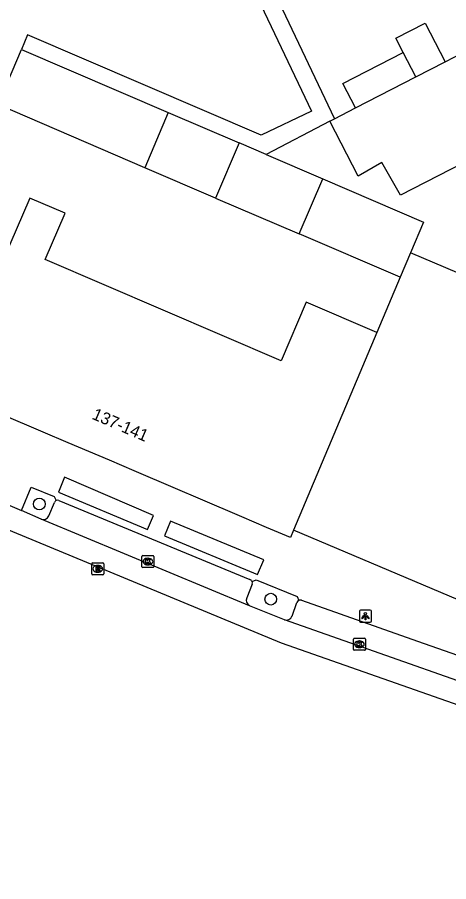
# Model space of a CAD drawing. Extents: x 161771 to 163125, y 382479 to 383177.
# Drawn here: x 162290.1 to 162326.1, y 382570.3 to 382642.4 of the extents above; entities that cross this region are included whole.
import ezdxf

# ---------------------------------------------------------------- set-up
doc = ezdxf.new("R2010")
doc.units = 0
for name, color, linetype in [('IMGEO_Boom', 7, 'Continuous'), ('IMGEO_Kolk', 7, 'Continuous'), ('IMGEO_Lichtpunt', 7, 'Continuous'), ('IMGEO_Pand', 7, 'Continuous'), ('IMGEO_Pand_nummerreeks', 7, 'Continuous'), ('IMGEO_Parkeervlak_open', 7, 'Continuous'), ('IMGEO_Rijbaan_lokaal_gesloten', 7, 'Continuous'), ('IMGEO_Rioolput', 7, 'Continuous'), ('IMGEO_Voetpad_open', 7, 'Continuous')]:
    doc.layers.add(name, color=color, linetype=linetype)

msp = doc.modelspace()

# ---------------------------------------------------------------- linework, layer by layer
at = {"layer": 'IMGEO_Boom'}
for centre in [(162291.967, 382601.804), (162311.264, 382593.877)]:
    msp.add_circle(centre, 0.489, dxfattribs=at)
at = {"layer": 'IMGEO_Kolk'}
for p, q in [((162300.598, 382597.509), (162301.45, 382597.509)), ((162300.523, 382596.583), (162300.523, 382597.435)), ((162301.011, 382597.289), (162301.036, 382597.289)), ((162301.524, 382597.435), (162301.524, 382596.583)), ((162301.45, 382596.509), (162300.598, 382596.509)), ((162301.034, 382596.729), (162301.009, 382596.729)), ((162318.157, 382589.69), (162318.157, 382590.542)), ((162318.232, 382590.616), (162319.084, 382590.616)), ((162318.645, 382590.396), (162318.67, 382590.396)), ((162319.158, 382590.542), (162319.158, 382589.69)), ((162319.084, 382589.616), (162318.232, 382589.616)), ((162318.668, 382589.836), (162318.643, 382589.836))]:
    msp.add_line(p, q, dxfattribs=at)
for points in [[(162300.598, 382597.509), (162301.45, 382597.509)], [(162300.523, 382596.583), (162300.523, 382597.435)], [(162300.844, 382597.209), (162300.967, 382597.209), (162300.967, 382597.058), (162301.097, 382597.209), (162301.261, 382597.209), (162301.115, 382597.058), (162301.268, 382596.809), (162301.116, 382596.809), (162301.031, 382596.973), (162300.967, 382596.906), (162300.967, 382596.809), (162300.844, 382596.809), (162300.844, 382597.209)], [(162301.524, 382597.435), (162301.524, 382596.583)], [(162301.45, 382596.509), (162300.598, 382596.509)], [(162318.157, 382589.69), (162318.157, 382590.542)], [(162318.232, 382590.616), (162319.084, 382590.616)], [(162318.478, 382590.316), (162318.601, 382590.316), (162318.601, 382590.165), (162318.731, 382590.316), (162318.895, 382590.316), (162318.749, 382590.165), (162318.902, 382589.916), (162318.75, 382589.916), (162318.665, 382590.08), (162318.601, 382590.013), (162318.601, 382589.916), (162318.478, 382589.916), (162318.478, 382590.316)], [(162319.158, 382590.542), (162319.158, 382589.69)], [(162319.084, 382589.616), (162318.232, 382589.616)]]:
    msp.add_lwpolyline(points, dxfattribs=at)
for centre, start, end in [((162300.6, 382597.433), 91.55205, 178.44795), ((162300.6, 382597.433), 91.55205, 178.44795), ((162301.448, 382597.433), 1.55205, 88.44795), ((162301.448, 382597.433), 1.55205, 88.44795), ((162300.6, 382596.585), 181.55205, 268.44795), ((162300.6, 382596.585), 181.55205, 268.44795), ((162301.448, 382596.585), 271.55205, 358.44795), ((162301.448, 382596.585), 271.55205, 358.44795), ((162318.234, 382590.54), 91.55205, 178.44795), ((162318.234, 382590.54), 91.55205, 178.44795), ((162319.082, 382590.54), 1.55205, 88.44795), ((162319.082, 382590.54), 1.55205, 88.44795), ((162318.234, 382589.692), 181.55205, 268.44795), ((162318.234, 382589.692), 181.55205, 268.44795), ((162319.082, 382589.692), 271.55205, 358.44795), ((162319.082, 382589.692), 271.55205, 358.44795)]:
    msp.add_arc(centre, 0.0765, start, end, dxfattribs=at)
for centre, major_axis, ratio, start_param, end_param in [((162301.01, 382597.009), (-0.387, 0.002), 0.722429, 4.712389, 7.853982), ((162301.035, 382597.009), (-0.39, 0.002), 0.717154, 1.570796, 4.712389), ((162318.644, 382590.116), (-0.387, 0.002), 0.722429, 4.712389, 7.853982), ((162318.669, 382590.116), (-0.39, 0.002), 0.717154, 1.570796, 4.712389)]:
    msp.add_ellipse(centre, major_axis=major_axis, ratio=ratio, start_param=start_param, end_param=end_param, dxfattribs=at)
at = {"layer": 'IMGEO_Lichtpunt'}
for p, q in [((162318.662, 382592.866), (162318.662, 382592.059)), ((162318.662, 382592.866), (162318.662, 382592.059)), ((162319.564, 382592.961), (162318.756, 382592.961)), ((162319.564, 382592.961), (162318.756, 382592.961)), ((162319.658, 382592.059), (162319.658, 382592.866)), ((162319.658, 382592.059), (162319.658, 382592.866)), ((162318.756, 382591.965), (162319.564, 382591.965)), ((162318.756, 382591.965), (162319.564, 382591.965))]:
    msp.add_line(p, q, dxfattribs=at)
for points in [[(162319.036, 382592.53), (162319.075, 382592.502), (162318.887, 382592.24), (162318.849, 382592.267), (162319.036, 382592.53)], [(162319.138, 382592.482), (162319.185, 382592.482), (162319.185, 382592.16), (162319.138, 382592.16), (162319.138, 382592.482)], [(162319.248, 382592.502), (162319.286, 382592.529), (162319.473, 382592.267), (162319.434, 382592.239), (162319.248, 382592.502)]]:
    msp.add_lwpolyline(points, dxfattribs=at)
msp.add_circle((162319.161, 382592.664), 0.0994, dxfattribs=at)
for centre, start, end in [((162318.756, 382592.866), 90, 180), ((162318.756, 382592.866), 90, 180), ((162319.564, 382592.866), 0, 90), ((162319.564, 382592.866), 0, 90), ((162318.756, 382592.059), 180, 270), ((162318.756, 382592.059), 180, 270), ((162319.564, 382592.059), 270, 0), ((162319.564, 382592.059), 270, 360)]:
    msp.add_arc(centre, 0.0946, start, end, dxfattribs=at)
at = {"layer": 'IMGEO_Pand'}
for points in [[(162355.836, 382644.864), (162351.387, 382642.583), (162322.08, 382627.559), (162320.518, 382630.266), (162318.547, 382629.128), (162316.196, 382633.711)], [(162322.301, 382639.446), (162321.696, 382640.618), (162324.138, 382641.877), (162325.796, 382638.664)], [(162325.796, 382638.664), (162329.566, 382640.609)], [(162300.776, 382629.833), (162288.5, 382635.102), (162290.472, 382639.696)], [(162290.472, 382639.696), (162302.709, 382634.444)], [(162318.328, 382634.811), (162317.274, 382636.853), (162322.301, 382639.446)], [(162323.354, 382637.404), (162322.301, 382639.446)], [(162323.354, 382637.404), (162325.796, 382638.664)], [(162318.328, 382634.811), (162323.354, 382637.404)], [(162302.709, 382634.444), (162300.776, 382629.833)], [(162302.709, 382634.444), (162308.629, 382631.902)], [(162316.579, 382633.909), (162318.328, 382634.811)], [(162316.196, 382633.711), (162316.579, 382633.909)], [(162308.629, 382631.902), (162306.667, 382627.305)], [(162310.889, 382630.932), (162308.629, 382631.902)], [(162310.889, 382630.932), (162315.613, 382628.905)], [(162306.667, 382627.305), (162300.776, 382629.833)], [(162313.635, 382624.314), (162315.613, 382628.905)], [(162315.613, 382628.905), (162324.013, 382625.299), (162322.929, 382622.738)], [(162320.101, 382616.097), (162314.228, 382618.615), (162312.143, 382613.751), (162292.459, 382622.19), (162294.111, 382626.044), (162291.175, 382627.303), (162289.511, 382623.447), (162284.254, 382611.213)], [(162306.667, 382627.305), (162313.635, 382624.314)], [(162322.058, 382620.699), (162313.635, 382624.314)], [(162322.929, 382622.738), (162322.058, 382620.699)], [(162379.028, 382608.247), (162375.863, 382604.377), (162373.376, 382601.335), (162322.929, 382622.738)], [(162322.058, 382620.699), (162320.101, 382616.097)], [(162320.101, 382616.097), (162313.172, 382599.641)], [(162313.172, 382599.641), (162312.902, 382599.006), (162310.913, 382599.855), (162308.846, 382600.737), (162305.395, 382602.21), (162303.325, 382603.093), (162299.876, 382604.565), (162297.808, 382605.447), (162294.365, 382606.912), (162292.279, 382607.8), (162288.83, 382609.267), (162286.762, 382610.146), (162284.254, 382611.213)], [(162368.518, 382576.348), (162368.466, 382576.233), (162313.172, 382599.641)]]:
    msp.add_lwpolyline(points, dxfattribs=at)
at = {"layer": 'IMGEO_Parkeervlak_open'}
for points in [[(162292.774, 382600.819), (162293.221, 382601.933)], [(162309.725, 382595.123), (162309.258, 382593.996)], [(162313.036, 382592.464), (162313.451, 382593.597)]]:
    msp.add_lwpolyline(points, dxfattribs=at)
for centre, radius, start, end in [((162293.51, 382601.807), 0.315, 114.5801, 156.49753), ((162292.304, 382601.029), 0.514, 247.7872, 335.87512), ((162309.401, 382595.207), 0.335, 345.50052, 25.92067), ((162309.715, 382593.79), 0.501, 155.76764, 245.2114), ((162313.753, 382593.485), 0.321, 119.95346, 159.69697), ((162312.554, 382592.655), 0.518, 253.69279, 338.33551)]:
    msp.add_arc(centre, radius, start, end, dxfattribs=at)
at = {"layer": 'IMGEO_Rijbaan_lokaal_gesloten'}
for points in [[(162370.099, 382570.33), (162336, 382581.86), (162312.157, 382590.208), (162289.771, 382599.475), (162259.358, 382612.5), (162215.386, 382631.365)], [(162277.062, 382607.009), (162290.489, 382601.256)], [(162292.11, 382600.553), (162290.489, 382601.256)], [(162309.505, 382593.335), (162292.11, 382600.553)], [(162312.409, 382592.158), (162309.505, 382593.335)], [(162335.784, 382583.935), (162312.409, 382592.158)]]:
    msp.add_lwpolyline(points, dxfattribs=at)
at = {"layer": 'IMGEO_Rioolput'}
for p, q in [((162296.336, 382595.981), (162296.336, 382596.833)), ((162296.411, 382596.907), (162297.263, 382596.907)), ((162297.337, 382596.833), (162297.337, 382595.981)), ((162296.847, 382596.127), (162296.822, 382596.127)), ((162296.824, 382596.687), (162296.849, 382596.687)), ((162297.263, 382595.907), (162296.411, 382595.907))]:
    msp.add_line(p, q, dxfattribs=at)
for points in [[(162296.336, 382595.981), (162296.336, 382596.833)], [(162296.411, 382596.907), (162297.263, 382596.907)], [(162297.337, 382596.833), (162297.337, 382595.981)], [(162296.925, 382596.605), (162296.673, 382596.607), (162296.673, 382596.207)], [(162296.673, 382596.207), (162296.797, 382596.207), (162296.797, 382596.369), (162296.808, 382596.369)], [(162296.851, 382596.526), (162296.797, 382596.526), (162296.797, 382596.445)], [(162296.797, 382596.445), (162296.849, 382596.445)], [(162296.855, 382596.34), (162296.926, 382596.207), (162297.066, 382596.207), (162297.001, 382596.333)], [(162297.263, 382595.907), (162296.411, 382595.907)]]:
    msp.add_lwpolyline(points, dxfattribs=at)
for centre, radius, start, end in [((162296.413, 382596.831), 0.0765, 91.55205, 178.44795), ((162296.413, 382596.831), 0.0765, 91.55205, 178.44795), ((162297.261, 382596.831), 0.0765, 1.55205, 88.44795), ((162297.261, 382596.831), 0.0765, 1.55205, 88.44795), ((162296.807, 382596.316), 0.0533, 26.02933, 88.69889), ((162296.833, 382596.634), 0.19, 274.7715, 282.96867), ((162296.857, 382596.43), 0.0964, 77.00612, 93.18647), ((162296.871, 382596.487), 0.0378, 276.66336, 79.67722), ((162296.924, 382596.495), 0.109, 350.36119, 89.41601), ((162296.922, 382596.495), 0.112, 277.58423, 350.98172), ((162296.906, 382596.28), 0.108, 29.51342, 73.79051), ((162296.413, 382595.983), 0.0765, 181.55205, 268.44795), ((162296.413, 382595.983), 0.0765, 181.55205, 268.44795), ((162297.261, 382595.983), 0.0765, 271.55205, 358.44795), ((162297.261, 382595.983), 0.0765, 271.55205, 358.44795)]:
    msp.add_arc(centre, radius, start, end, dxfattribs=at)
for centre, major_axis, ratio, start_param, end_param in [((162296.823, 382596.407), (-0.387, 0.002), 0.722429, 4.712389, 7.853982), ((162296.848, 382596.407), (-0.39, 0.002), 0.717154, 1.570796, 4.712389)]:
    msp.add_ellipse(centre, major_axis=major_axis, ratio=ratio, start_param=start_param, end_param=end_param, dxfattribs=at)
at = {"layer": 'IMGEO_Voetpad_open'}
for points in [[(162303.606, 382661.182), (162306.204, 382655.72), (162316.579, 382633.909)], [(162303.644, 382657.729), (162309.892, 382644.595), (162314.672, 382634.545), (162310.473, 382632.548), (162290.992, 382640.907), (162290.472, 382639.696)], [(162316.196, 382633.711), (162310.889, 382630.932)], [(162301.001, 382599.674), (162301.497, 382600.856), (162294.072, 382604.052), (162293.559, 382602.788), (162301.001, 382599.674)], [(162290.489, 382601.256), (162291.279, 382603.215), (162293.199, 382602.424), (162293.379, 382602.094)], [(162293.596, 382602.109), (162309.513, 382595.526)], [(162302.913, 382600.365), (162302.418, 382599.147), (162310.146, 382595.927), (162310.674, 382597.159), (162302.913, 382600.365)], [(162309.702, 382595.353), (162310.041, 382595.49), (162313.473, 382594.096), (162313.592, 382593.764)], [(162313.828, 382593.798), (162323.501, 382590.382), (162335.732, 382586.104)]]:
    msp.add_lwpolyline(points, dxfattribs=at)
for centre, radius, start, end in [((162293.508, 382601.81), 0.312, 73.56625, 114.34224), ((162309.392, 382595.204), 0.343, 25.63, 69.43153), ((162313.752, 382593.489), 0.318, 76.18027, 120.21586)]:
    msp.add_arc(centre, radius, start, end, dxfattribs=at)

# ---------------------------------------------------------------- texts
at = {"layer": 'IMGEO_Pand_nummerreeks'}
msp.add_text('137-141', height=1, rotation=336.54884, dxfattribs=at).set_placement((162296.286, 382608.927))

doc.saveas('drawing.dxf')
